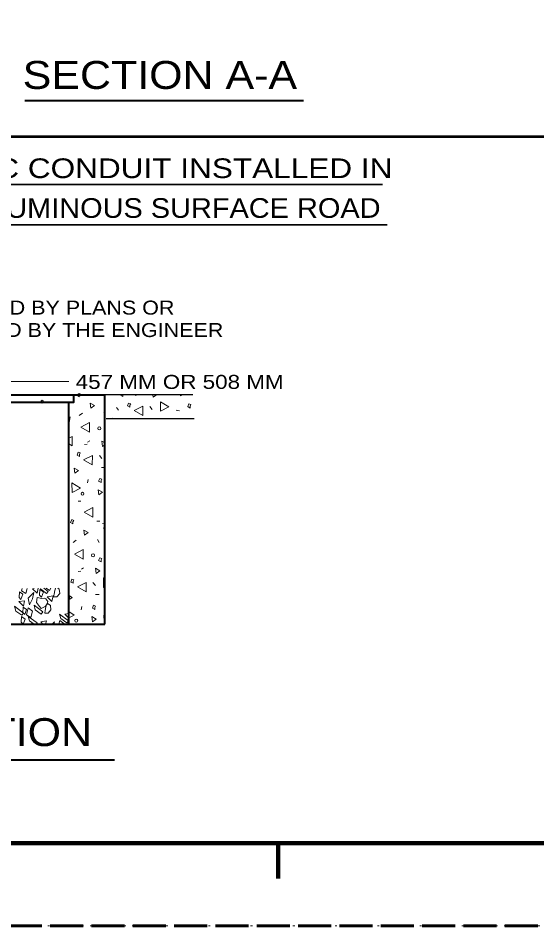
# Model space of a CAD drawing. Extents: x 312583 to 312854, y 144419 to 144597.
# Drawn here: x 312713.21 to 312741.44, y 144418.58 to 144467.96 of the extents above; entities that cross this region are included whole.
import ezdxf
from ezdxf.enums import TextEntityAlignment as Align

# ---------------------------------------------------------------- set-up
doc = ezdxf.new("R2010")
doc.units = 0
doc.header["$LTSCALE"] = 0.3
doc.header["$PDMODE"] = 32
doc.header["$PDSIZE"] = 0.15
doc.linetypes.add('DOTTED', pattern=[1.5, 0.3, -1.2])
doc.linetypes.add('LONG_DASHED', pattern=[7.5, 6, -1.5])
for name, color, linetype, lineweight in [('1', 7, 'Continuous', 40), ('2', 7, 'Continuous', 13), ('63', 7, 'DOTTED', 13)]:
    doc.layers.add(name, color=color, linetype=linetype, lineweight=lineweight)

msp = doc.modelspace()

# ---------------------------------------------------------------- linework, layer by layer
at = {"layer": '1', "lineweight": 53}
msp.add_line((312742.1369, 144461.5065), (312616.5, 144461.5065), dxfattribs=at)
at = {"layer": '1'}
msp.add_line((312708.2912, 144434.9934), (312717.9205, 144434.9934), dxfattribs=at)
at = {"layer": '1', "lineweight": 158}
for p, q in [((312616.5, 144423.0846), (312849, 144423.0846)), ((312727.35, 144421.1646), (312727.35, 144423.0846))]:
    msp.add_line(p, q, dxfattribs=at)
at = {"layer": '1', "linetype": 'LONG_DASHED', "lineweight": 60}
msp.add_line((312851.75, 144418.5846), (312583.526, 144418.5846), dxfattribs=at)
at = {"layer": '2', "lineweight": 40}
for p, q in [((312713.5706, 144463.4849), (312728.7367, 144463.4849)), ((312716.2415, 144447.4671), (312717.9205, 144447.4671)), ((312718.444, 144427.5906), (312630.5394, 144427.5906))]:
    msp.add_line(p, q, dxfattribs=at)
at = {"layer": '2', "lineweight": 35}
for p, q in [((312699.4822, 144458.9188), (312733.0455, 144458.9188)), ((312699.5818, 144456.7201), (312733.2936, 144456.7201))]:
    msp.add_line(p, q, dxfattribs=at)
at = {"layer": '2'}
for p, q in [((312707.2792, 144448.2031), (312715.9655, 144448.2031)), ((312718.7408, 144447.4671), (312718.9018, 144447.3751)), ((312718.9018, 144447.3751), (312718.9018, 144447.4671)), ((312719.5765, 144447.4364), (312719.7145, 144447.4671)), ((312720.5348, 144447.4671), (312720.5502, 144447.3367)), ((312720.5502, 144447.3367), (312720.7342, 144447.4671)), ((312722.0222, 144447.4671), (312722.0375, 144447.4134)), ((312722.0375, 144447.4134), (312722.1065, 144447.4671)), ((312718.5645, 144446.7771), (312718.6718, 144446.6391)), ((312720.3738, 144446.8384), (312720.5042, 144446.6774)), ((312721.8075, 144446.6391), (312721.9838, 144446.6007)), ((312716.0422, 144446.2787), (312715.9732, 144445.8417)), ((312716.7168, 144446.4704), (312716.5328, 144446.3401)), ((312717.8745, 144446.5087), (312717.9205, 144446.4167)), ((312720.4965, 144446.1867), (312720.7112, 144446.1867)), ((312715.9578, 144444.8067), (312716.1495, 144444.6994)), ((312716.8165, 144444.7607), (312716.9622, 144444.7914)), ((312716.9852, 144444.8911), (312717.1155, 144444.9601)), ((312717.7978, 144444.6611), (312717.9205, 144444.7454)), ((312717.6292, 144444.1627), (312717.7518, 144444.0017)), ((312717.7442, 144443.5111), (312717.9205, 144443.5111)), ((312716.9852, 144442.6754), (312717.0082, 144442.8594)), ((312716.4638, 144441.6864), (312716.6172, 144441.6941)), ((312717.4835, 144440.5901), (312717.6445, 144440.5977)), ((312717.8055, 144440.4674), (312717.9205, 144440.4981)), ((312716.3718, 144439.5704), (312716.1955, 144439.4324)), ((312717.5295, 144439.6087), (312717.6138, 144439.4401)), ((312716.4792, 144437.8531), (312716.6248, 144437.8837)), ((312716.6478, 144437.9834), (312716.7705, 144438.0524)), ((312717.2765, 144437.2551), (312717.4068, 144437.0941)), ((312717.9205, 144437.4774), (312717.8515, 144437.5157)), ((312713.3895, 144436.8027), (312713.4202, 144436.9407)), ((312714.0795, 144436.9407), (312713.9798, 144436.9254)), ((312714.4168, 144436.9407), (312714.4398, 144436.8947)), ((312717.4068, 144436.6034), (312717.6138, 144436.6111)), ((312715.9732, 144436.1281), (312715.9578, 144436.1357)), ((312716.6402, 144435.7677), (312716.6708, 144435.9517)), ((312715.9655, 144435.5837), (312715.7508, 144435.5454)), ((312715.7508, 144435.5454), (312715.9655, 144435.3307)), ((312713.8265, 144435.1774), (312714.0718, 144435.0011)), ((312714.4322, 144435.1237), (312714.5548, 144434.9934))]:
    msp.add_line(p, q, dxfattribs=at)
at = {"layer": '2', "lineweight": 25}
for p, q in [((312722.7122, 144447.4671), (312717.9205, 144447.4671)), ((312722.7812, 144446.1714), (312717.9972, 144446.1714))]:
    msp.add_line(p, q, dxfattribs=at)
at = {"layer": '2', "lineweight": 40}
for points in [[(312710.0085, 144447.4671), (312712.9755, 144447.4671), (312716.2415, 144447.4671)], [(312710.0085, 144447.0684), (312712.9755, 144447.0684), (312716.2415, 144447.0684), (312716.2415, 144447.4671)], [(312717.9205, 144434.9934), (312717.9205, 144442.8441), (312717.9205, 144447.4671)], [(312715.9578, 144434.9934), (312715.9578, 144442.8441), (312715.9578, 144447.0684)]]:
    msp.add_lwpolyline(points, dxfattribs=at)
at = {"layer": '2'}
for points in [[(312716.4178, 144447.4671), (312716.4025, 144447.4364), (312716.5328, 144447.3597), (312716.5328, 144447.4671)], [(312718.3422, 144446.1714), (312718.2962, 144446.2021), (312718.2962, 144446.1714)], [(312716.1495, 144444.6994), (312716.1418, 144445.2131), (312715.9578, 144445.1211)], [(312717.9205, 144444.8527), (312717.7672, 144444.9524), (312717.7978, 144444.6611)], [(312717.9205, 144440.1991), (312717.8745, 144440.1837), (312717.8822, 144440.3371)], [(312717.8515, 144437.5157), (312717.8515, 144436.9944), (312717.9205, 144437.0327)], [(312713.6962, 144436.9407), (312713.6272, 144436.6571), (312713.3895, 144436.8027)], [(312713.9798, 144436.9254), (312714.2328, 144436.6877), (312714.2942, 144436.9484)], [(312714.4398, 144436.8947), (312714.7542, 144436.6571), (312714.8462, 144436.7797), (312714.6085, 144436.9484)], [(312714.7388, 144436.9484), (312714.9075, 144436.8257), (312714.9918, 144436.9484), (312714.9842, 144436.9484)], [(312715.2372, 144436.9561), (312715.1988, 144436.8334), (312715.1682, 144436.6264), (312715.1375, 144436.4807), (312715.3138, 144436.4807), (312715.4748, 144436.6724), (312715.4442, 144436.9024), (312715.3675, 144436.9561)], [(312715.9578, 144436.5267), (312716.0268, 144436.5574), (312715.9732, 144436.1281)], [(312715.9578, 144436.3121), (312716.1418, 144436.4424), (312715.9578, 144436.5497)], [(312714.1868, 144434.9934), (312714.2328, 144435.0624), (312713.7498, 144435.4151), (312713.8265, 144435.1774)], [(312715.9578, 144435.3384), (312716.2568, 144435.4917), (312715.9578, 144435.6757)], [(312717.9205, 144435.3537), (312717.8668, 144435.3154), (312717.8668, 144435.4764)], [(312713.9338, 144435.0011), (312713.9415, 144435.0241), (312713.7805, 144434.9934)], [(312714.7005, 144434.9934), (312714.7465, 144435.1774), (312714.4322, 144435.1237)], [(312715.0608, 144434.9934), (312715.1835, 144435.1237), (312715.1528, 144434.9934)], [(312715.4135, 144434.9934), (312715.4672, 144435.2004), (312715.6972, 144435.0241), (312715.6895, 144434.9934)]]:
    msp.add_lwpolyline(points, dxfattribs=at)
for points in [[(312717.1692, 144446.7387), (312717.3685, 144446.8844), (312717.1308, 144447.0224)], [(312719.2928, 144446.9074), (312719.3388, 144446.9841), (312719.2162, 144447.0224), (312719.1625, 144446.8691), (312719.2928, 144446.8001)], [(312719.9982, 144446.3401), (312719.9982, 144446.8537), (312719.5228, 144446.6161)], [(312720.9488, 144447.0914), (312720.9488, 144446.5777), (312721.4088, 144446.8154)], [(312722.5665, 144446.8614), (312722.6125, 144446.9381), (312722.4898, 144446.9764), (312722.4362, 144446.8307), (312722.5665, 144446.7541)], [(312717.0925, 144445.4354), (312717.0925, 144445.9567), (312716.6248, 144445.7191)], [(312716.5405, 144444.2317), (312716.5788, 144444.3084), (312716.4638, 144444.3467), (312716.4178, 144444.1934), (312716.5405, 144444.1244)], [(312717.2382, 144443.6567), (312717.2458, 144444.1781), (312716.7705, 144443.9404)], [(312716.2952, 144443.2044), (312716.4868, 144443.3501), (312716.2492, 144443.4881)], [(312716.1342, 144442.6754), (312716.1418, 144442.1617), (312716.6018, 144442.3994)], [(312717.7212, 144442.8134), (312717.7672, 144442.8901), (312717.6445, 144442.9207), (312717.5832, 144442.7751), (312717.7212, 144442.6984)], [(312717.5985, 144442.0237), (312717.7902, 144442.1694), (312717.5525, 144442.3074)], [(312717.2688, 144440.8201), (312717.2765, 144441.3337), (312716.8012, 144441.0961)], [(312716.1878, 144440.5671), (312716.2338, 144440.6361), (312716.1188, 144440.6821), (312716.0575, 144440.5287), (312716.1878, 144440.4597)], [(312716.8242, 144439.8311), (312717.0235, 144439.9767), (312716.7858, 144440.1147)], [(312716.7475, 144438.5277), (312716.7475, 144439.0491), (312716.2798, 144438.8114)], [(312717.7212, 144438.4971), (312717.7672, 144438.5737), (312717.6445, 144438.6121), (312717.5832, 144438.4511), (312717.7212, 144438.3897)], [(312717.4605, 144437.7534), (312717.6522, 144437.8991), (312717.4145, 144438.0447)], [(312716.1955, 144437.3317), (312716.2415, 144437.4084), (312716.1265, 144437.4391), (312716.0652, 144437.2857), (312716.1955, 144437.2167)], [(312716.9008, 144436.7567), (312716.9085, 144437.2704), (312716.4332, 144437.0327)], [(312713.2745, 144436.7491), (312713.2592, 144436.4424), (312713.3588, 144436.3351), (312713.4585, 144436.6187)], [(312714.3938, 144436.8794), (312714.3708, 144436.5651), (312714.4782, 144436.4731), (312714.5855, 144436.7491)], [(312713.2438, 144436.2201), (312713.4892, 144435.9671), (312713.5582, 144436.2737)], [(312713.7498, 144436.4117), (312714.0565, 144436.7184), (312713.9798, 144436.3811), (312713.8265, 144436.0437)], [(312714.3708, 144435.9594), (312714.4552, 144435.8521), (312714.6698, 144435.9594), (312714.7772, 144436.0897), (312714.8155, 144436.2201), (312714.7158, 144436.3811), (312714.6315, 144436.4117), (312714.4935, 144436.3964), (312714.2482, 144436.4424), (312714.2098, 144436.1664)], [(312714.7848, 144436.4807), (312715.0302, 144436.2354), (312715.1068, 144436.5421)], [(312713.0828, 144435.7064), (312713.4048, 144435.4764), (312713.4892, 144435.5914), (312713.0062, 144435.9671)], [(312713.4738, 144435.9287), (312713.4662, 144435.6221), (312713.5658, 144435.5224), (312713.6655, 144435.7984)], [(312713.6655, 144435.5071), (312713.7575, 144435.8827), (312713.9875, 144435.7064), (312713.9032, 144435.3614)], [(312714.1408, 144435.7831), (312714.4628, 144435.5454), (312714.5548, 144435.6681), (312714.0718, 144436.0361)], [(312714.7925, 144436.1357), (312714.7158, 144435.9441), (312714.6852, 144435.7371), (312714.6545, 144435.5914), (312714.8385, 144435.5914), (312714.9918, 144435.7831), (312714.9612, 144436.0131)], [(312717.3762, 144435.9057), (312717.4145, 144435.9824), (312717.2995, 144436.0207), (312717.2458, 144435.8674), (312717.3762, 144435.7984)], [(312713.3895, 144435.4074), (312713.3742, 144435.1007), (312713.4738, 144435.0011), (312713.5812, 144435.2694)], [(312715.5362, 144435.3001), (312715.8582, 144435.0624), (312715.9425, 144435.1851), (312715.4595, 144435.5454)], [(312717.2535, 144435.1161), (312717.4528, 144435.2694), (312717.2152, 144435.4074)]]:
    msp.add_lwpolyline(points, close=True, dxfattribs=at)
for centre, radius in [((312717.6259, 144445.6454), 0.0867), ((312716.7093, 144442.0916), 0.0785), ((312717.2835, 144438.7405), 0.0867), ((312716.3669, 144435.1868), 0.0785)]:
    msp.add_circle(centre, radius, dxfattribs=at)
for p in [(312714.5088, 144447.0991), (312716.5328, 144447.4671)]:
    msp.add_point(p, dxfattribs=at)
at = {"layer": '63'}
msp.add_lwpolyline([(312601.2, 144418.5846), (312853.5, 144418.5846), (312853.5, 144596.7846)], dxfattribs=at)

# ---------------------------------------------------------------- texts
at = {"layer": '2', "width": 1.15}
for s, p in [('SECTION A-A', (312720.9198, 144464.1117)), ('CONDUITS AND TYPICAL JUNCTION BOXES (457 BY 914 MM) INSTALLATION', (312674.431, 144428.3625))]:
    msp.add_text(s, height=1.52, dxfattribs=at).set_placement(p, align=Align.CENTER)
at = {"layer": '2'}
for s, height, width, p in [('RIGID METALLIC CONDUIT INSTALLED IN', 1.07, 1.2, (312699.6125, 144459.2617)), ('SUBBASE OF BITUMINOUS SURFACE ROAD', 1.07, 1.1, (312699.6125, 144457.0985)), ('AS REQUIRED BY PLANS OR ', 0.76, 1.15, (312705.5388, 144451.8361)), ('AS DIRECTED BY THE ENGINEER', 0.76, 1.15, (312705.5388, 144450.6161)), ('457 MM OR 508 MM', 0.76, 1.2, (312716.3374, 144447.7941))]:
    msp.add_text(s, height=height, dxfattribs=dict(at, width=width)).set_placement(p)

doc.saveas('drawing.dxf')
